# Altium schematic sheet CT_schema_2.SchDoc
size 307 x 173 mm
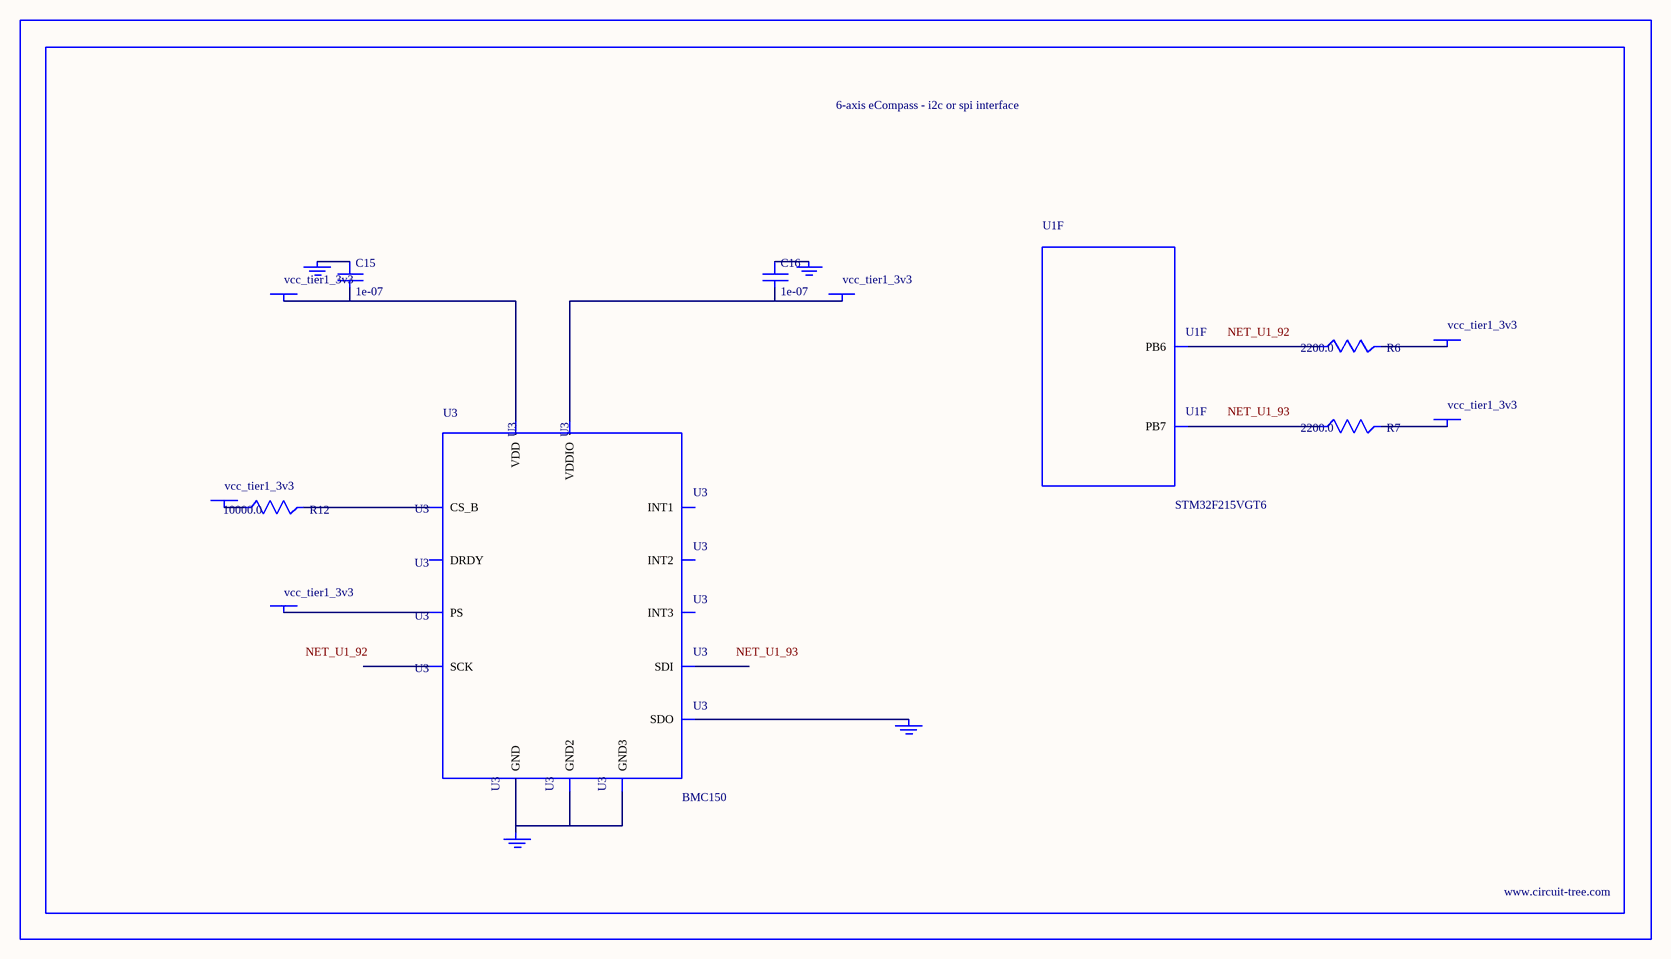
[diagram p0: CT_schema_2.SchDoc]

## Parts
BORDER1  (no value)
C15  1e-07  [C0402]
C16  1e-07  [C0402]
GND_INSTANCE_1_0  (no value)
GND_INSTANCE_1_1  (no value)
GND_INSTANCE_1_2  (no value)
GND_INSTANCE_1_3  (no value)
POWER_INSTANCE_1_0  vcc_tier1_3v3
POWER_INSTANCE_1_1  vcc_tier1_3v3
POWER_INSTANCE_1_2  vcc_tier1_3v3
POWER_INSTANCE_1_3  vcc_tier1_3v3
POWER_INSTANCE_1_4  vcc_tier1_3v3
POWER_INSTANCE_1_5  vcc_tier1_3v3
R6  2200.0  [R0603]
R7  2200.0  [R0603]
R12  10000.0  [R0603]
U1  STM32F215VGT6  [LQFP100]  (part F of 10)
U3  BMC150  [LGA14R35P5X6_200X200X100]

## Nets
NetC15_1: C15.1 GND_INSTANCE_1_1.0(GND)
NetC15_2: C15.2 POWER_INSTANCE_1_0.0(PWR) U3.8(VDD)
NetC16_1: C16.1 GND_INSTANCE_1_2.0(GND)
NetC16_2: C16.2 POWER_INSTANCE_1_1.0(PWR) U3.10(VDDIO)
NetGND_INSTANCE_1_0_0: GND_INSTANCE_1_0.0(GND) U3.1(SDO)
NetGND_INSTANCE_1_3_0: GND_INSTANCE_1_3.0(GND) U3.6(GND) U3.7(GND2) U3.9(GND3)
NetPOWER_INSTANCE_1_2_0: POWER_INSTANCE_1_2.0(PWR) R12.1
NetPOWER_INSTANCE_1_3_0: POWER_INSTANCE_1_3.0(PWR) U3.13(PS)
NetPOWER_INSTANCE_1_4_0: POWER_INSTANCE_1_4.0(PWR) R6.2
NetPOWER_INSTANCE_1_5_0: POWER_INSTANCE_1_5.0(PWR) R7.2
NetR6_1: R6.1 U1.92(PB6)
NetR7_1: R7.1 U1.93(PB7)
NetR12_2: R12.2 U3.12(CS_B)

Not connected (* = marked no-connect by the designer): U3 2(INT1) 3(INT2) 4(DRDY) 5(INT3) 11(SCK) 14(SDI)

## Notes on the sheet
- Labels drawn without touching a wire or pin: NET_U1_92, NET_U1_93

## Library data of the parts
BORDER1 = BORDER_PAGE1
C15 C16 = C0402C104K3RACTU
GND_INSTANCE_1_0-GND_INSTANCE_1_3 = GND
POWER_INSTANCE_1_0-POWER_INSTANCE_1_5 = PWR
R6 R7 = RC0603JR-072K2L
R12 = RC0603JR-0710KL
